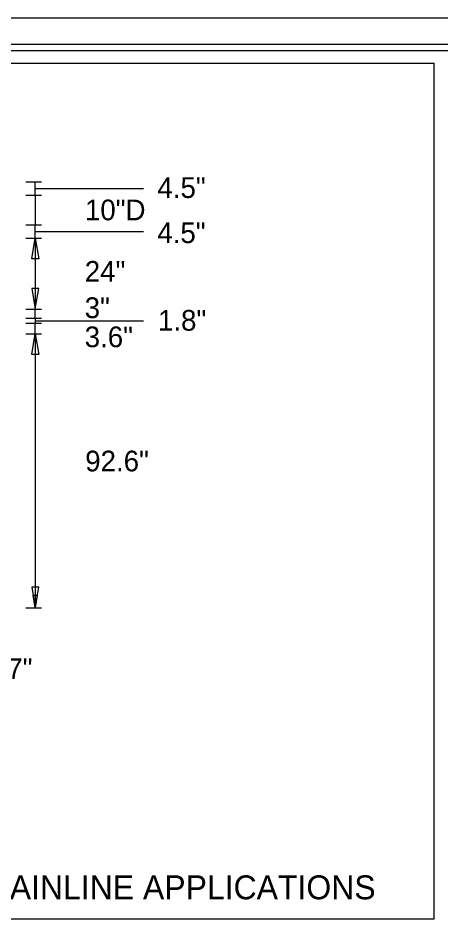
# Model space of a CAD drawing. Extents: x 17890459 to 17890580, y 17897938 to 17898017.
# Drawn here: x 17890507.47 to 17890519.38, y 17897991.76 to 17898017.37 of the extents above; entities that cross this region are included whole.
import ezdxf

# ---------------------------------------------------------------- set-up
doc = ezdxf.new("R2010")
doc.units = 0
for name, color, linetype in [('Default', 7, 'Continuous'), ('GSDims', 7, 'Continuous'), ('PlotBorder_dp', 7, 'Continuous'), ('SheetBorder_dp', 7, 'Continuous'), ('SheetLinesMisc2_dp', 7, 'Continuous')]:
    doc.layers.add(name, color=color, linetype=linetype)

msp = doc.modelspace()

# ---------------------------------------------------------------- linework, layer by layer
at = {"layer": 'Default'}
msp.add_line((17890508.069, 17898001.315), (17890508.069, 17898001.315), dxfattribs=at)
at = {"layer": 'GSDims'}
for p, q in [((17890507.689, 17898012.751), (17890508.126, 17898012.751)), ((17890507.951, 17898012.376), (17890507.951, 17898012.751)), ((17890507.689, 17898012.376), (17890508.126, 17898012.376)), ((17890507.689, 17898012.376), (17890508.126, 17898012.376)), ((17890507.951, 17898012.563), (17890510.997, 17898012.563)), ((17890507.951, 17898012.376), (17890507.951, 17898011.542)), ((17890507.689, 17898011.542), (17890508.126, 17898011.542)), ((17890507.689, 17898011.542), (17890508.126, 17898011.542)), ((17890507.951, 17898011.167), (17890507.951, 17898011.542)), ((17890507.951, 17898011.355), (17890510.997, 17898011.355)), ((17890507.689, 17898011.167), (17890508.126, 17898011.167)), ((17890507.689, 17898011.167), (17890508.126, 17898011.167)), ((17890507.951, 17898011.167), (17890507.951, 17898009.163)), ((17890507.689, 17898009.163), (17890508.126, 17898009.163)), ((17890507.689, 17898009.163), (17890508.126, 17898009.163)), ((17890507.951, 17898008.913), (17890507.951, 17898009.163)), ((17890507.689, 17898008.913), (17890508.126, 17898008.913)), ((17890507.689, 17898008.913), (17890508.126, 17898008.913)), ((17890507.689, 17898008.768), (17890508.126, 17898008.768)), ((17890507.689, 17898008.768), (17890508.126, 17898008.768)), ((17890507.951, 17898008.913), (17890507.951, 17898008.768)), ((17890507.951, 17898008.84), (17890510.997, 17898008.84)), ((17890507.951, 17898008.466), (17890507.951, 17898008.768)), ((17890507.689, 17898008.466), (17890508.126, 17898008.466)), ((17890507.689, 17898008.466), (17890508.126, 17898008.466)), ((17890507.951, 17898008.466), (17890507.951, 17898000.751)), ((17890507.689, 17898000.751), (17890508.126, 17898000.751))]:
    msp.add_line(p, q, dxfattribs=at)
for points in [[(17890507.951, 17898011.167), (17890508.048, 17898010.584), (17890507.854, 17898010.584)], [(17890507.951, 17898009.163), (17890508.048, 17898009.747), (17890507.854, 17898009.747)], [(17890507.951, 17898008.466), (17890508.048, 17898007.883), (17890507.854, 17898007.883)], [(17890507.951, 17898000.751), (17890508.048, 17898001.334), (17890507.854, 17898001.334)], [(17890507.951, 17898000.751), (17890507.893, 17898001.101), (17890508.009, 17898001.101)]]:
    msp.add_lwpolyline(points, close=True, dxfattribs=at)
at = {"layer": 'PlotBorder_dp'}
msp.add_lwpolyline([(17890458.908, 17897939.544), (17890580.045, 17897939.544), (17890580.045, 17898017.365), (17890458.908, 17898017.365)], close=True, dxfattribs=at)
at = {"layer": 'SheetBorder_dp'}
msp.add_line((17890462.946, 17898016.631), (17890576.007, 17898016.631), dxfattribs=at)
at = {"layer": 'SheetLinesMisc2_dp'}
for p, q in [((17890463.151, 17898016.456), (17890575.98, 17898016.456)), ((17890463.151, 17898016.456), (17890575.98, 17898016.456)), ((17890480.814, 17898016.097), (17890519.188, 17898016.097)), ((17890519.188, 17897991.984), (17890519.188, 17898016.097)), ((17890480.814, 17897991.984), (17890519.188, 17897991.984))]:
    msp.add_line(p, q, dxfattribs=at)

# ---------------------------------------------------------------- texts
at = {"layer": 'GSDims'}
for s, height, p in [('4.5"', 0.5833, (17890511.392, 17898012.299)), ('10"D', 0.5833, (17890509.35, 17898011.67)), ('4.5"', 0.5833, (17890511.389, 17898011.027)), ('24"', 0.5833, (17890509.346, 17898009.938)), ('3"', 0.5833, (17890509.343, 17898008.914)), ('1.8"', 0.5833, (17890511.408, 17898008.559)), ('3.6"', 0.5833, (17890509.343, 17898008.093)), ('92.6"', 0.5833, (17890509.358, 17898004.594)), ('5.7"', 0.5833, (17890506.512, 17897998.743)), ('MAINLINE APPLICATIONS', 0.67331, (17890506.483, 17897992.536))]:
    msp.add_text(s, height=height, dxfattribs=at).set_placement(p)

doc.saveas('drawing.dxf')
